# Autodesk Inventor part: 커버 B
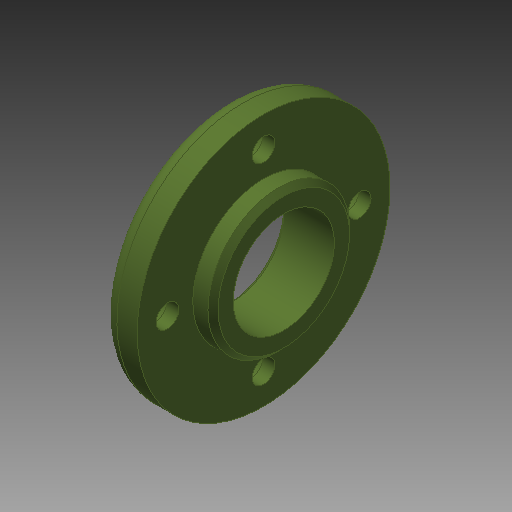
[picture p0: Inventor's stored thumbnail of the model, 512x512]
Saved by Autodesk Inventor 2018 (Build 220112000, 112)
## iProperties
Created: 2019-01
Part Number: 커버 B
Material: 알루미늄 6061
Document SubType Name: Modeling
Designer: mduedu
Density: 2.71 g/cm^3
Appearance: 올리브 녹색
Mass: 30.6342 g
Surface Area: 56.15 cm^2
Volume: 11.3041 cm^3
Author: mduedu
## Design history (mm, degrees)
sketch "스케치1"
  geometry: L1 (0, 0)-(7, 0); L2 (7, 0)-(7, 25); L3 (7, 25)-(0, 25); L4 (0, 25)-(0, 0); L5 (7, 0)-(11, 0); L6 (11, 0)-(11, 14); L7 (11, 14)-(7, 14); L8 (7, 14)-(7, 0)
  constraints: 16 end point, 4 parallel, 2 horizontal, 2 perpendicular
  dimensions: "d0" = 50 diameter of L3 L1; "d2" = 11 distance between parallel lines of L6 L4; "d3" = 7 distance of L2.end L3.end; "d4" = 28 diameter of L7 L5
revolve "회전1" sketch "스케치1" stored, may be unused: angle "d5" = 90 deg
sketch "스케치2"
  geometry: C1 r 10 at (0, 0); 1 further point
  constraints: 1 centre point, 1 coincident
  dimensions: "d6" = 20 diameter of C1
extrude "돌출1" cut sketch "스케치2" extent not by distance; stored distance "d7" = 10; taper "d8" = 0 deg
chamfer "모따기1" distance "d9" = 1; stored, may be unused: second distance "d10" = 2, angle "d11" = 45 deg
fillet "모깎기1" dims "d12" = 3
sketch "스케치3" dims "d13" = 38
  geometry: 6 further points
  constraints: 2 vertical alignment, 1 coincident, 7 other
  dimensions: "d16" = 360 deg dimension on point (0, 0) point (0, 19) (derived)
chamfer "모따기2" distance "d18" = 1; stored, may be unused: second distance "d19" = 2, angle "d20" = 45 deg
sketch "스케치4"
  geometry: 4 further points
  constraints: 4 other
hole "구멍1" sketch "스케치4" at (-19, 0), (0, -19), (19, 0), (0, 19) diameter "d21" = 4.5; stored, may be unused: countersink angle "d25" = 90 deg, drill point angle "d27" = 0 deg; dims "d22" = 6, "d23" = 8, "d24" = 4.6, "d26" = 8
node "솔리드1"
